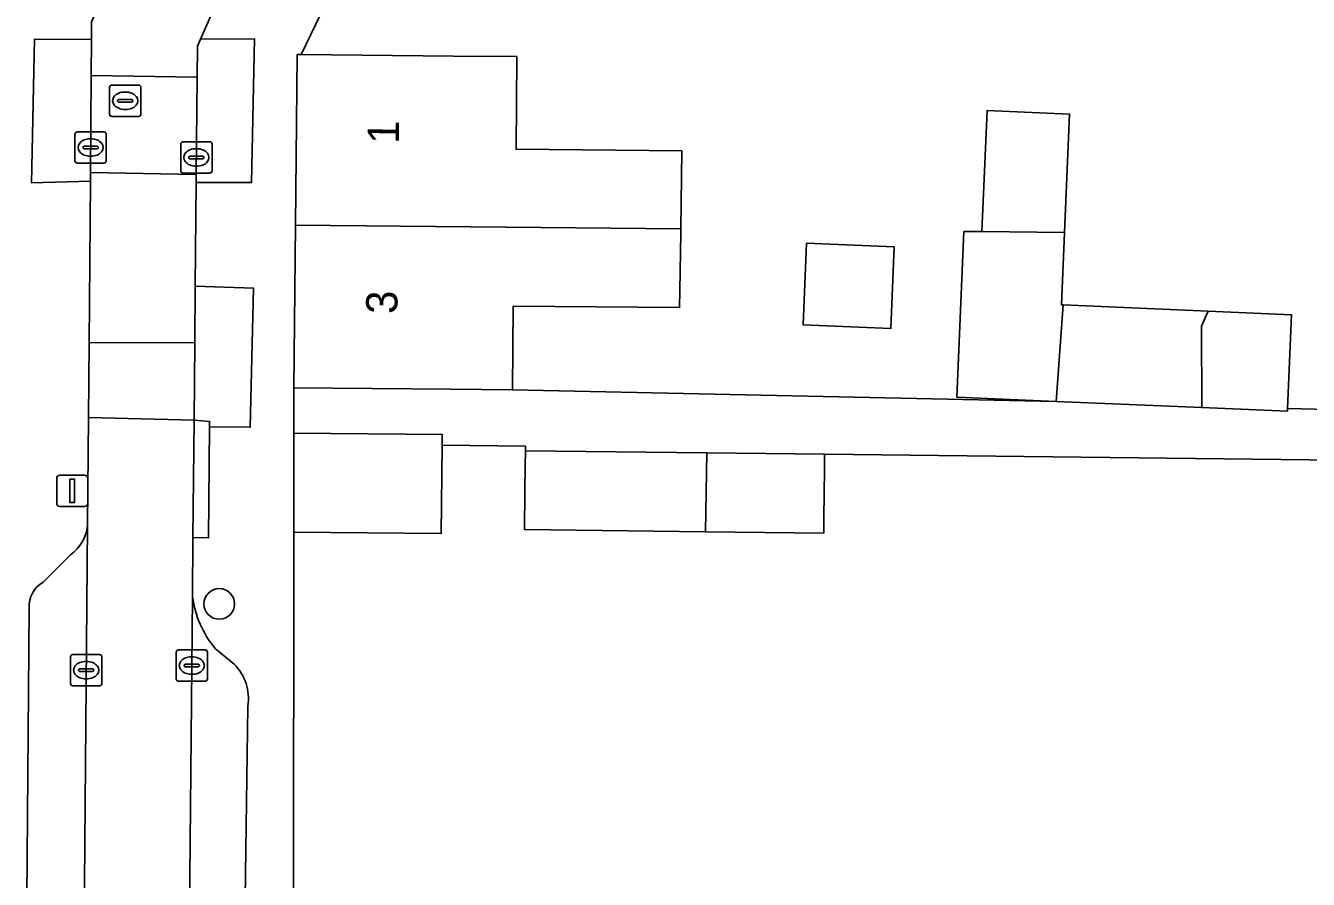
# Model space of a CAD drawing. Extents: x 161838 to 162344, y 381620 to 382160.
# Drawn here: x 162129.45 to 162170.43, y 381650.93 to 381678.21 of the extents above; entities that cross this region are included whole.
import ezdxf

# ---------------------------------------------------------------- set-up
doc = ezdxf.new("R2010")
doc.units = 0
for name, color, linetype in [('IMGEO_Boom', 7, 'Continuous'), ('IMGEO_Erf', 7, 'Continuous'), ('IMGEO_Kolk', 7, 'Continuous'), ('IMGEO_Lichtmast', 7, 'Continuous'), ('IMGEO_Muur', 7, 'Continuous'), ('IMGEO_Pand', 7, 'Continuous'), ('IMGEO_Pand_nummerreeks', 7, 'Continuous'), ('IMGEO_Parkeervlak_open', 7, 'Continuous'), ('IMGEO_Rijbaan_lokaal_open', 7, 'Continuous'), ('IMGEO_Rioolput', 7, 'Continuous'), ('IMGEO_Voetpad_open', 7, 'Continuous')]:
    doc.layers.add(name, color=color, linetype=linetype)

msp = doc.modelspace()

# ---------------------------------------------------------------- linework, layer by layer
at = {"layer": 'IMGEO_Boom'}
msp.add_circle((162135.636, 381659.729), 0.489, dxfattribs=at)
at = {"layer": 'IMGEO_Erf'}
for points in [[(162138.863, 381678.543), (162138.254, 381677.285), (162143.125, 381677.238), (162145.147, 381677.219), (162145.118, 381674.257), (162150.413, 381674.207), (162150.389, 381671.718), (162150.388, 381671.573), (162150.349, 381669.749), (162150.343, 381669.197), (162145.031, 381669.248), (162145.006, 381666.572), (162162.379, 381666.199), (162159.203, 381666.335), (162159.429, 381671.633), (162160.004, 381671.628), (162160.17, 381675.495), (162162.804, 381675.382), (162162.643, 381671.603), (162162.544, 381669.286), (162162.599, 381669.283), (162167.235, 381669.085), (162169.897, 381668.972), (162169.769, 381665.971), (162175.381, 381665.835)], [(162171.387, 381664.319), (162154.979, 381664.517), (162154.977, 381664.363), (162154.975, 381664.185), (162154.973, 381664.02), (162154.956, 381662.482), (162154.95, 381661.994), (162151.173, 381662.038), (162145.389, 381662.105), (162145.39, 381662.215), (162145.413, 381664.229), (162145.417, 381664.537), (162145.418, 381664.622), (162145.417, 381664.767), (162142.757, 381664.798), (162142.729, 381661.975), (162138.018, 381662.02), (162138.004, 381650.126)]]:
    msp.add_lwpolyline(points, dxfattribs=at)
msp.add_lwpolyline([(162154.399, 381671.259), (162157.2, 381671.139), (162157.089, 381668.529), (162154.288, 381668.649)], close=True, dxfattribs=at)
at = {"layer": 'IMGEO_Kolk'}
for p, q in [((162131.026, 381673.889), (162131.026, 381674.741)), ((162131.101, 381674.815), (162131.953, 381674.815)), ((162131.514, 381674.595), (162131.539, 381674.595)), ((162132.027, 381674.741), (162132.027, 381673.889)), ((162134.405, 381673.572), (162134.405, 381674.424)), ((162134.48, 381674.498), (162135.332, 381674.498)), ((162135.406, 381674.424), (162135.406, 381673.572)), ((162131.285, 381674.309), (162131.285, 381674.321)), ((162131.723, 381674.272), (162131.325, 381674.272)), ((162131.328, 381674.358), (162131.726, 381674.358)), ((162131.537, 381674.035), (162131.512, 381674.035)), ((162131.769, 381674.321), (162131.769, 381674.309)), ((162134.707, 381674.041), (162135.105, 381674.041)), ((162134.893, 381674.278), (162134.918, 381674.278)), ((162131.953, 381673.815), (162131.101, 381673.815)), ((162134.664, 381673.992), (162134.664, 381674.004)), ((162135.102, 381673.955), (162134.704, 381673.955)), ((162134.916, 381673.718), (162134.891, 381673.718)), ((162135.148, 381674.004), (162135.148, 381673.992)), ((162135.332, 381673.498), (162134.48, 381673.498)), ((162130.884, 381657.186), (162130.884, 381658.038)), ((162130.959, 381658.112), (162131.811, 381658.112)), ((162131.885, 381658.038), (162131.885, 381657.186)), ((162134.259, 381657.333), (162134.259, 381658.185)), ((162134.334, 381658.259), (162135.186, 381658.259)), ((162134.747, 381658.039), (162134.772, 381658.039)), ((162135.26, 381658.185), (162135.26, 381657.333)), ((162131.143, 381657.606), (162131.143, 381657.618)), ((162131.186, 381657.655), (162131.584, 381657.655)), ((162131.372, 381657.892), (162131.397, 381657.892)), ((162131.627, 381657.618), (162131.627, 381657.606)), ((162134.518, 381657.753), (162134.518, 381657.765)), ((162134.956, 381657.716), (162134.558, 381657.716)), ((162134.561, 381657.802), (162134.959, 381657.802)), ((162135.002, 381657.765), (162135.002, 381657.753)), ((162131.581, 381657.569), (162131.183, 381657.569)), ((162131.395, 381657.332), (162131.37, 381657.332)), ((162135.186, 381657.259), (162134.334, 381657.259)), ((162134.77, 381657.479), (162134.745, 381657.479)), ((162131.811, 381657.112), (162130.959, 381657.112))]:
    msp.add_line(p, q, dxfattribs=at)
for points in [[(162131.026, 381673.889), (162131.026, 381674.741)], [(162131.101, 381674.815), (162131.953, 381674.815)], [(162132.027, 381674.741), (162132.027, 381673.889)], [(162134.405, 381673.572), (162134.405, 381674.424)], [(162134.48, 381674.498), (162135.332, 381674.498)], [(162135.406, 381674.424), (162135.406, 381673.572)], [(162131.953, 381673.815), (162131.101, 381673.815)], [(162135.332, 381673.498), (162134.48, 381673.498)], [(162130.884, 381657.186), (162130.884, 381658.038)], [(162130.959, 381658.112), (162131.811, 381658.112)], [(162131.885, 381658.038), (162131.885, 381657.186)], [(162134.259, 381657.333), (162134.259, 381658.185)], [(162134.334, 381658.259), (162135.186, 381658.259)], [(162135.26, 381658.185), (162135.26, 381657.333)], [(162135.186, 381657.259), (162134.334, 381657.259)], [(162131.811, 381657.112), (162130.959, 381657.112)]]:
    msp.add_lwpolyline(points, dxfattribs=at)
for centre, radius, start, end in [((162131.103, 381674.739), 0.0765, 91.552, 178.448), ((162131.103, 381674.739), 0.0765, 91.552, 178.448), ((162131.951, 381674.739), 0.0765, 1.552, 88.448), ((162131.951, 381674.739), 0.0765, 1.552, 88.448), ((162134.482, 381674.422), 0.0765, 91.552, 178.448), ((162134.482, 381674.422), 0.0765, 91.552, 178.448), ((162135.33, 381674.422), 0.0765, 1.552, 88.448), ((162135.33, 381674.422), 0.0765, 1.552, 88.448), ((162131.325, 381674.318), 0.0403, 85.8775, 175.7526), ((162131.322, 381674.308), 0.0366, 178.938, 274.7102), ((162131.726, 381674.315), 0.043, 264.8664, 352.4533), ((162131.73, 381674.32), 0.0386, 1.7309, 96.639), ((162134.704, 381674.001), 0.0403, 85.8775, 175.7526), ((162135.109, 381674.003), 0.0386, 1.7309, 96.639), ((162131.103, 381673.891), 0.0765, 181.552, 268.448), ((162131.103, 381673.891), 0.0765, 181.552, 268.448), ((162131.951, 381673.891), 0.0765, 271.552, 358.448), ((162131.951, 381673.891), 0.0765, 271.552, 358.448), ((162134.701, 381673.991), 0.0366, 178.938, 274.7102), ((162135.105, 381673.998), 0.043, 264.8664, 352.4533), ((162134.482, 381673.574), 0.0765, 181.552, 268.448), ((162134.482, 381673.574), 0.0765, 181.552, 268.448), ((162135.33, 381673.574), 0.0765, 271.552, 358.448), ((162135.33, 381673.574), 0.0765, 271.552, 358.448), ((162130.961, 381658.036), 0.0765, 91.552, 178.448), ((162130.961, 381658.036), 0.0765, 91.552, 178.448), ((162131.809, 381658.036), 0.0765, 1.552, 88.448), ((162131.809, 381658.036), 0.0765, 1.552, 88.448), ((162134.336, 381658.183), 0.0765, 91.552, 178.448), ((162134.336, 381658.183), 0.0765, 91.552, 178.448), ((162135.184, 381658.183), 0.0765, 1.552, 88.448), ((162135.184, 381658.183), 0.0765, 1.552, 88.448), ((162131.183, 381657.615), 0.0403, 85.8775, 175.7526), ((162131.588, 381657.617), 0.0386, 1.7309, 96.639), ((162134.558, 381657.762), 0.0403, 85.8775, 175.7526), ((162134.555, 381657.752), 0.0366, 178.938, 274.7102), ((162134.959, 381657.759), 0.043, 264.8664, 352.4533), ((162134.963, 381657.764), 0.0386, 1.7309, 96.639), ((162131.18, 381657.605), 0.0366, 178.938, 274.7102), ((162131.584, 381657.612), 0.043, 264.8664, 352.4533), ((162134.336, 381657.335), 0.0765, 181.552, 268.448), ((162134.336, 381657.335), 0.0765, 181.552, 268.448), ((162135.184, 381657.335), 0.0765, 271.552, 358.448), ((162135.184, 381657.335), 0.0765, 271.552, 358.448), ((162130.961, 381657.188), 0.0765, 181.552, 268.448), ((162130.961, 381657.188), 0.0765, 181.552, 268.448), ((162131.809, 381657.188), 0.0765, 271.552, 358.448), ((162131.809, 381657.188), 0.0765, 271.552, 358.448)]:
    msp.add_arc(centre, radius, start, end, dxfattribs=at)
for centre, major_axis, ratio, start_param, end_param in [((162131.513, 381674.315), (-0.387, 0.002), 0.722429, 4.712389, 7.853982), ((162131.538, 381674.315), (-0.39, 0.002), 0.717154, 1.570796, 4.712389), ((162134.892, 381673.998), (-0.387, 0.002), 0.722429, 4.712389, 7.853982), ((162134.917, 381673.998), (-0.39, 0.002), 0.717154, 1.570796, 4.712389), ((162134.746, 381657.759), (-0.387, 0.002), 0.722429, 4.712389, 7.853982), ((162134.771, 381657.759), (-0.39, 0.002), 0.717154, 1.570796, 4.712389), ((162131.371, 381657.612), (-0.387, 0.002), 0.722429, 4.712389, 7.853982), ((162131.396, 381657.612), (-0.39, 0.002), 0.717154, 1.570796, 4.712389)]:
    msp.add_ellipse(centre, major_axis=major_axis, ratio=ratio, start_param=start_param, end_param=end_param, dxfattribs=at)
at = {"layer": 'IMGEO_Lichtmast'}
for p, q in [((162130.542, 381663.844), (162131.332, 381663.844)), ((162131.332, 381663.844), (162130.542, 381663.844)), ((162130.442, 381662.944), (162130.442, 381663.744)), ((162130.442, 381663.744), (162130.442, 381662.944)), ((162131.432, 381663.744), (162131.432, 381662.944)), ((162131.432, 381662.944), (162131.432, 381663.744)), ((162131.332, 381662.844), (162130.542, 381662.844)), ((162130.542, 381662.844), (162131.332, 381662.844))]:
    msp.add_line(p, q, dxfattribs=at)
msp.add_lwpolyline([(162130.862, 381663.719), (162131.012, 381663.719), (162131.012, 381662.969), (162130.862, 381662.969), (162130.862, 381663.719)], dxfattribs=at)
for centre, start, end in [((162130.542, 381663.744), 90, 180), ((162130.542, 381663.744), 90, 180), ((162131.332, 381663.744), 0, 90), ((162131.332, 381663.744), 360, 90), ((162130.542, 381662.944), 180, 270), ((162130.542, 381662.944), 180, 270), ((162131.332, 381662.944), 270, 0), ((162131.332, 381662.944), 270, 0)]:
    msp.add_arc(centre, 0.1, start, end, dxfattribs=at)
at = {"layer": 'IMGEO_Muur'}
msp.add_lwpolyline([(162138.004, 381650.126), (162138.018, 381662.02)], dxfattribs=at)
at = {"layer": 'IMGEO_Pand'}
for points in [[(162138.073, 381671.834), (162150.389, 381671.718), (162150.413, 381674.207), (162145.118, 381674.257), (162145.147, 381677.219), (162143.125, 381677.238), (162138.254, 381677.285), (162138.125, 381677.286)], [(162162.804, 381675.382), (162160.17, 381675.495), (162160.004, 381671.628), (162162.643, 381671.603)], [(162150.349, 381669.749), (162150.388, 381671.573), (162150.389, 381671.718), (162138.073, 381671.834), (162138.023, 381666.639), (162143.023, 381666.591), (162145.006, 381666.572), (162145.031, 381669.248), (162150.343, 381669.197)], [(162162.599, 381669.283), (162162.544, 381669.286), (162162.643, 381671.603), (162160.004, 381671.628), (162159.429, 381671.633), (162159.203, 381666.335), (162162.379, 381666.199)], [(162154.399, 381671.259), (162154.288, 381668.649), (162157.089, 381668.529), (162157.2, 381671.139)], [(162167.235, 381669.085), (162162.599, 381669.283), (162162.379, 381666.199), (162167.032, 381666.001), (162167.021, 381668.61)], [(162169.897, 381668.972), (162167.235, 381669.085), (162167.021, 381668.61), (162167.032, 381666.001), (162169.765, 381665.884), (162169.769, 381665.971)], [(162142.757, 381664.798), (162142.76, 381665.145), (162138.022, 381665.19), (162138.018, 381662.02), (162142.729, 381661.975)], [(162151.214, 381664.561), (162145.418, 381664.622), (162145.417, 381664.537), (162145.413, 381664.229), (162145.39, 381662.215), (162145.389, 381662.105), (162151.173, 381662.038)], [(162154.979, 381664.517), (162151.214, 381664.561), (162151.173, 381662.038), (162154.95, 381661.994), (162154.956, 381662.482), (162154.973, 381664.02), (162154.975, 381664.185), (162154.977, 381664.363)]]:
    msp.add_lwpolyline(points, close=True, dxfattribs=at)
at = {"layer": 'IMGEO_Parkeervlak_open'}
for points in [[(162131.554, 381677.767), (162129.729, 381677.772), (162129.634, 381673.189), (162131.517, 381673.236), (162131.519, 381673.515), (162131.545, 381676.614)], [(162134.901, 381673.199), (162136.666, 381673.194), (162136.761, 381677.79), (162135.04, 381677.774), (162134.941, 381677.55), (162134.932, 381676.563), (162134.903, 381673.454)], [(162134.87, 381669.886), (162134.854, 381668.084), (162134.831, 381665.601), (162135.329, 381665.564), (162135.327, 381665.392), (162136.624, 381665.374), (162136.732, 381669.817)]]:
    msp.add_lwpolyline(points, close=True, dxfattribs=at)
for points in [[(162131.255, 381641.888), (162131.425, 381662.241)], [(162130.878, 381661.3), (162130.006, 381660.42)], [(162134.779, 381659.958), (162134.634, 381644.305)], [(162129.565, 381659.606), (162129.45, 381644.981)], [(162136.11, 381657.806), (162135.511, 381658.298)], [(162136.422, 381647.245), (162136.547, 381656.462)]]:
    msp.add_lwpolyline(points, dxfattribs=at)
for centre, radius, start, end in [((162130.156, 381662.349), 1.274, 304.5365, 355.1249), ((162130.418, 381659.67), 0.856, 118.7987, 184.3063), ((162138.027, 381660.399), 3.277, 187.7279, 219.8636), ((162135.029, 381656.711), 1.539, 350.6704, 45.3534)]:
    msp.add_arc(centre, radius, start, end, dxfattribs=at)
at = {"layer": 'IMGEO_Rijbaan_lokaal_open'}
for points in [[(162131.554, 381677.767), (162131.545, 381676.614), (162134.932, 381676.563), (162134.941, 381677.55), (162135.04, 381677.774), (162137.204, 381682.696), (162135.396, 381683.525), (162134.123, 381684.109), (162131.559, 381678.326)], [(162131.545, 381676.614), (162131.519, 381673.515), (162134.903, 381673.454), (162134.932, 381676.563)], [(162134.87, 381669.886), (162134.901, 381673.199), (162134.903, 381673.454), (162131.519, 381673.515), (162131.517, 381673.236), (162131.474, 381668.069), (162134.854, 381668.084)], [(162134.831, 381665.601), (162134.854, 381668.084), (162131.474, 381668.069), (162131.454, 381665.682)], [(162134.831, 381665.601), (162131.454, 381665.682), (162131.425, 381662.241), (162131.255, 381641.888), (162131.222, 381637.892), (162134.574, 381637.814), (162134.634, 381644.305), (162134.779, 381659.958), (162134.796, 381661.85)]]:
    msp.add_lwpolyline(points, close=True, dxfattribs=at)
at = {"layer": 'IMGEO_Rioolput'}
for p, q in [((162132.13, 381675.383), (162132.13, 381676.235)), ((162132.205, 381676.309), (162133.057, 381676.309)), ((162132.618, 381676.089), (162132.643, 381676.089)), ((162133.131, 381676.235), (162133.131, 381675.383)), ((162132.389, 381675.803), (162132.389, 381675.815)), ((162132.827, 381675.766), (162132.429, 381675.766)), ((162132.432, 381675.852), (162132.83, 381675.852)), ((162132.873, 381675.815), (162132.873, 381675.803)), ((162133.057, 381675.309), (162132.205, 381675.309)), ((162132.641, 381675.529), (162132.616, 381675.529))]:
    msp.add_line(p, q, dxfattribs=at)
for points in [[(162132.13, 381675.383), (162132.13, 381676.235)], [(162132.205, 381676.309), (162133.057, 381676.309)], [(162133.131, 381676.235), (162133.131, 381675.383)], [(162133.057, 381675.309), (162132.205, 381675.309)]]:
    msp.add_lwpolyline(points, dxfattribs=at)
for centre, radius, start, end in [((162132.207, 381676.233), 0.0765, 91.552, 178.448), ((162132.207, 381676.233), 0.0765, 91.552, 178.448), ((162133.055, 381676.233), 0.0765, 1.552, 88.448), ((162133.055, 381676.233), 0.0765, 1.552, 88.448), ((162132.429, 381675.812), 0.0403, 85.8775, 175.7526), ((162132.426, 381675.802), 0.0366, 178.938, 274.7102), ((162132.83, 381675.809), 0.043, 264.8664, 352.4533), ((162132.834, 381675.814), 0.0386, 1.7309, 96.639), ((162132.207, 381675.385), 0.0765, 181.552, 268.448), ((162132.207, 381675.385), 0.0765, 181.552, 268.448), ((162133.055, 381675.385), 0.0765, 271.552, 358.448), ((162133.055, 381675.385), 0.0765, 271.552, 358.448)]:
    msp.add_arc(centre, radius, start, end, dxfattribs=at)
for centre, major_axis, ratio, start_param, end_param in [((162132.617, 381675.809), (-0.387, 0.002), 0.722429, 4.712389, 7.853982), ((162132.642, 381675.809), (-0.39, 0.002), 0.717154, 1.570796, 4.712389)]:
    msp.add_ellipse(centre, major_axis=major_axis, ratio=ratio, start_param=start_param, end_param=end_param, dxfattribs=at)
at = {"layer": 'IMGEO_Voetpad_open'}
for points in [[(162138.022, 381665.19), (162138.023, 381666.639), (162138.073, 381671.834), (162138.125, 381677.286), (162138.254, 381677.285), (162138.863, 381678.543), (162140.679, 381682.649), (162140.685, 381682.662), (162145.306, 381693.112), (162145.886, 381694.369), (162150.664, 381704.961), (162148.366, 381706.622), (162147.084, 381704.658), (162146.567, 381703.517)], [(162131.425, 381662.241), (162131.454, 381665.682), (162131.474, 381668.069), (162131.517, 381673.236), (162129.634, 381673.189), (162129.729, 381677.772), (162131.554, 381677.767), (162131.559, 381678.326), (162134.123, 381684.109), (162135.06, 381686.312), (162135.388, 381687.036), (162135.434, 381687.138)], [(162138.548, 381685.808), (162138.16, 381684.951), (162137.204, 381682.696), (162135.04, 381677.774), (162136.761, 381677.79), (162136.666, 381673.194), (162134.901, 381673.199), (162134.87, 381669.886), (162136.732, 381669.817), (162136.624, 381665.374), (162135.327, 381665.392), (162135.295, 381661.845), (162134.796, 381661.85), (162134.779, 381659.958)], [(162175.381, 381665.835), (162169.769, 381665.971), (162169.765, 381665.884), (162167.032, 381666.001), (162162.379, 381666.199), (162145.006, 381666.572), (162143.023, 381666.591), (162138.023, 381666.639), (162138.022, 381665.19), (162142.76, 381665.145), (162142.757, 381664.798), (162145.417, 381664.767), (162145.418, 381664.622), (162151.214, 381664.561), (162154.979, 381664.517), (162171.387, 381664.319)], [(162134.634, 381644.305), (162134.574, 381637.814), (162137.885, 381637.977), (162138.004, 381650.126), (162138.018, 381662.02), (162138.022, 381665.19)], [(162130.006, 381660.42), (162130.878, 381661.3)], [(162129.45, 381644.981), (162129.565, 381659.606)], [(162135.511, 381658.298), (162136.11, 381657.806)], [(162136.547, 381656.462), (162136.422, 381647.245)]]:
    msp.add_lwpolyline(points, dxfattribs=at)
msp.add_lwpolyline([(162134.831, 381665.601), (162134.796, 381661.85), (162135.295, 381661.845), (162135.327, 381665.392), (162135.329, 381665.564)], close=True, dxfattribs=at)
for centre, radius, start, end in [((162130.156, 381662.349), 1.274, 304.5365, 355.1249), ((162130.418, 381659.67), 0.856, 118.7987, 184.3063), ((162138.027, 381660.399), 3.277, 187.7279, 219.8636), ((162135.029, 381656.711), 1.539, 350.6704, 45.3534)]:
    msp.add_arc(centre, radius, start, end, dxfattribs=at)

# ---------------------------------------------------------------- texts
at = {"layer": 'IMGEO_Pand_nummerreeks'}
for s, rotation, p in [('1', 89.4511, (162141.377, 381674.431)), ('3', 89.4502, (162141.326, 381668.994))]:
    msp.add_text(s, height=1, rotation=rotation, dxfattribs=at).set_placement(p)

doc.saveas('drawing.dxf')
